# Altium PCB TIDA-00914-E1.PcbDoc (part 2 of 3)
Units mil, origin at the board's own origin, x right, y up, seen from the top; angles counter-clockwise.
Board outline 6575 x 7007.88 mil, 4 copper layers (Top Layer, GND, PWR, Bottom Layer), stack 79.834 mil thick; 302 components, 122 nets, 688 pads, 184 vias.
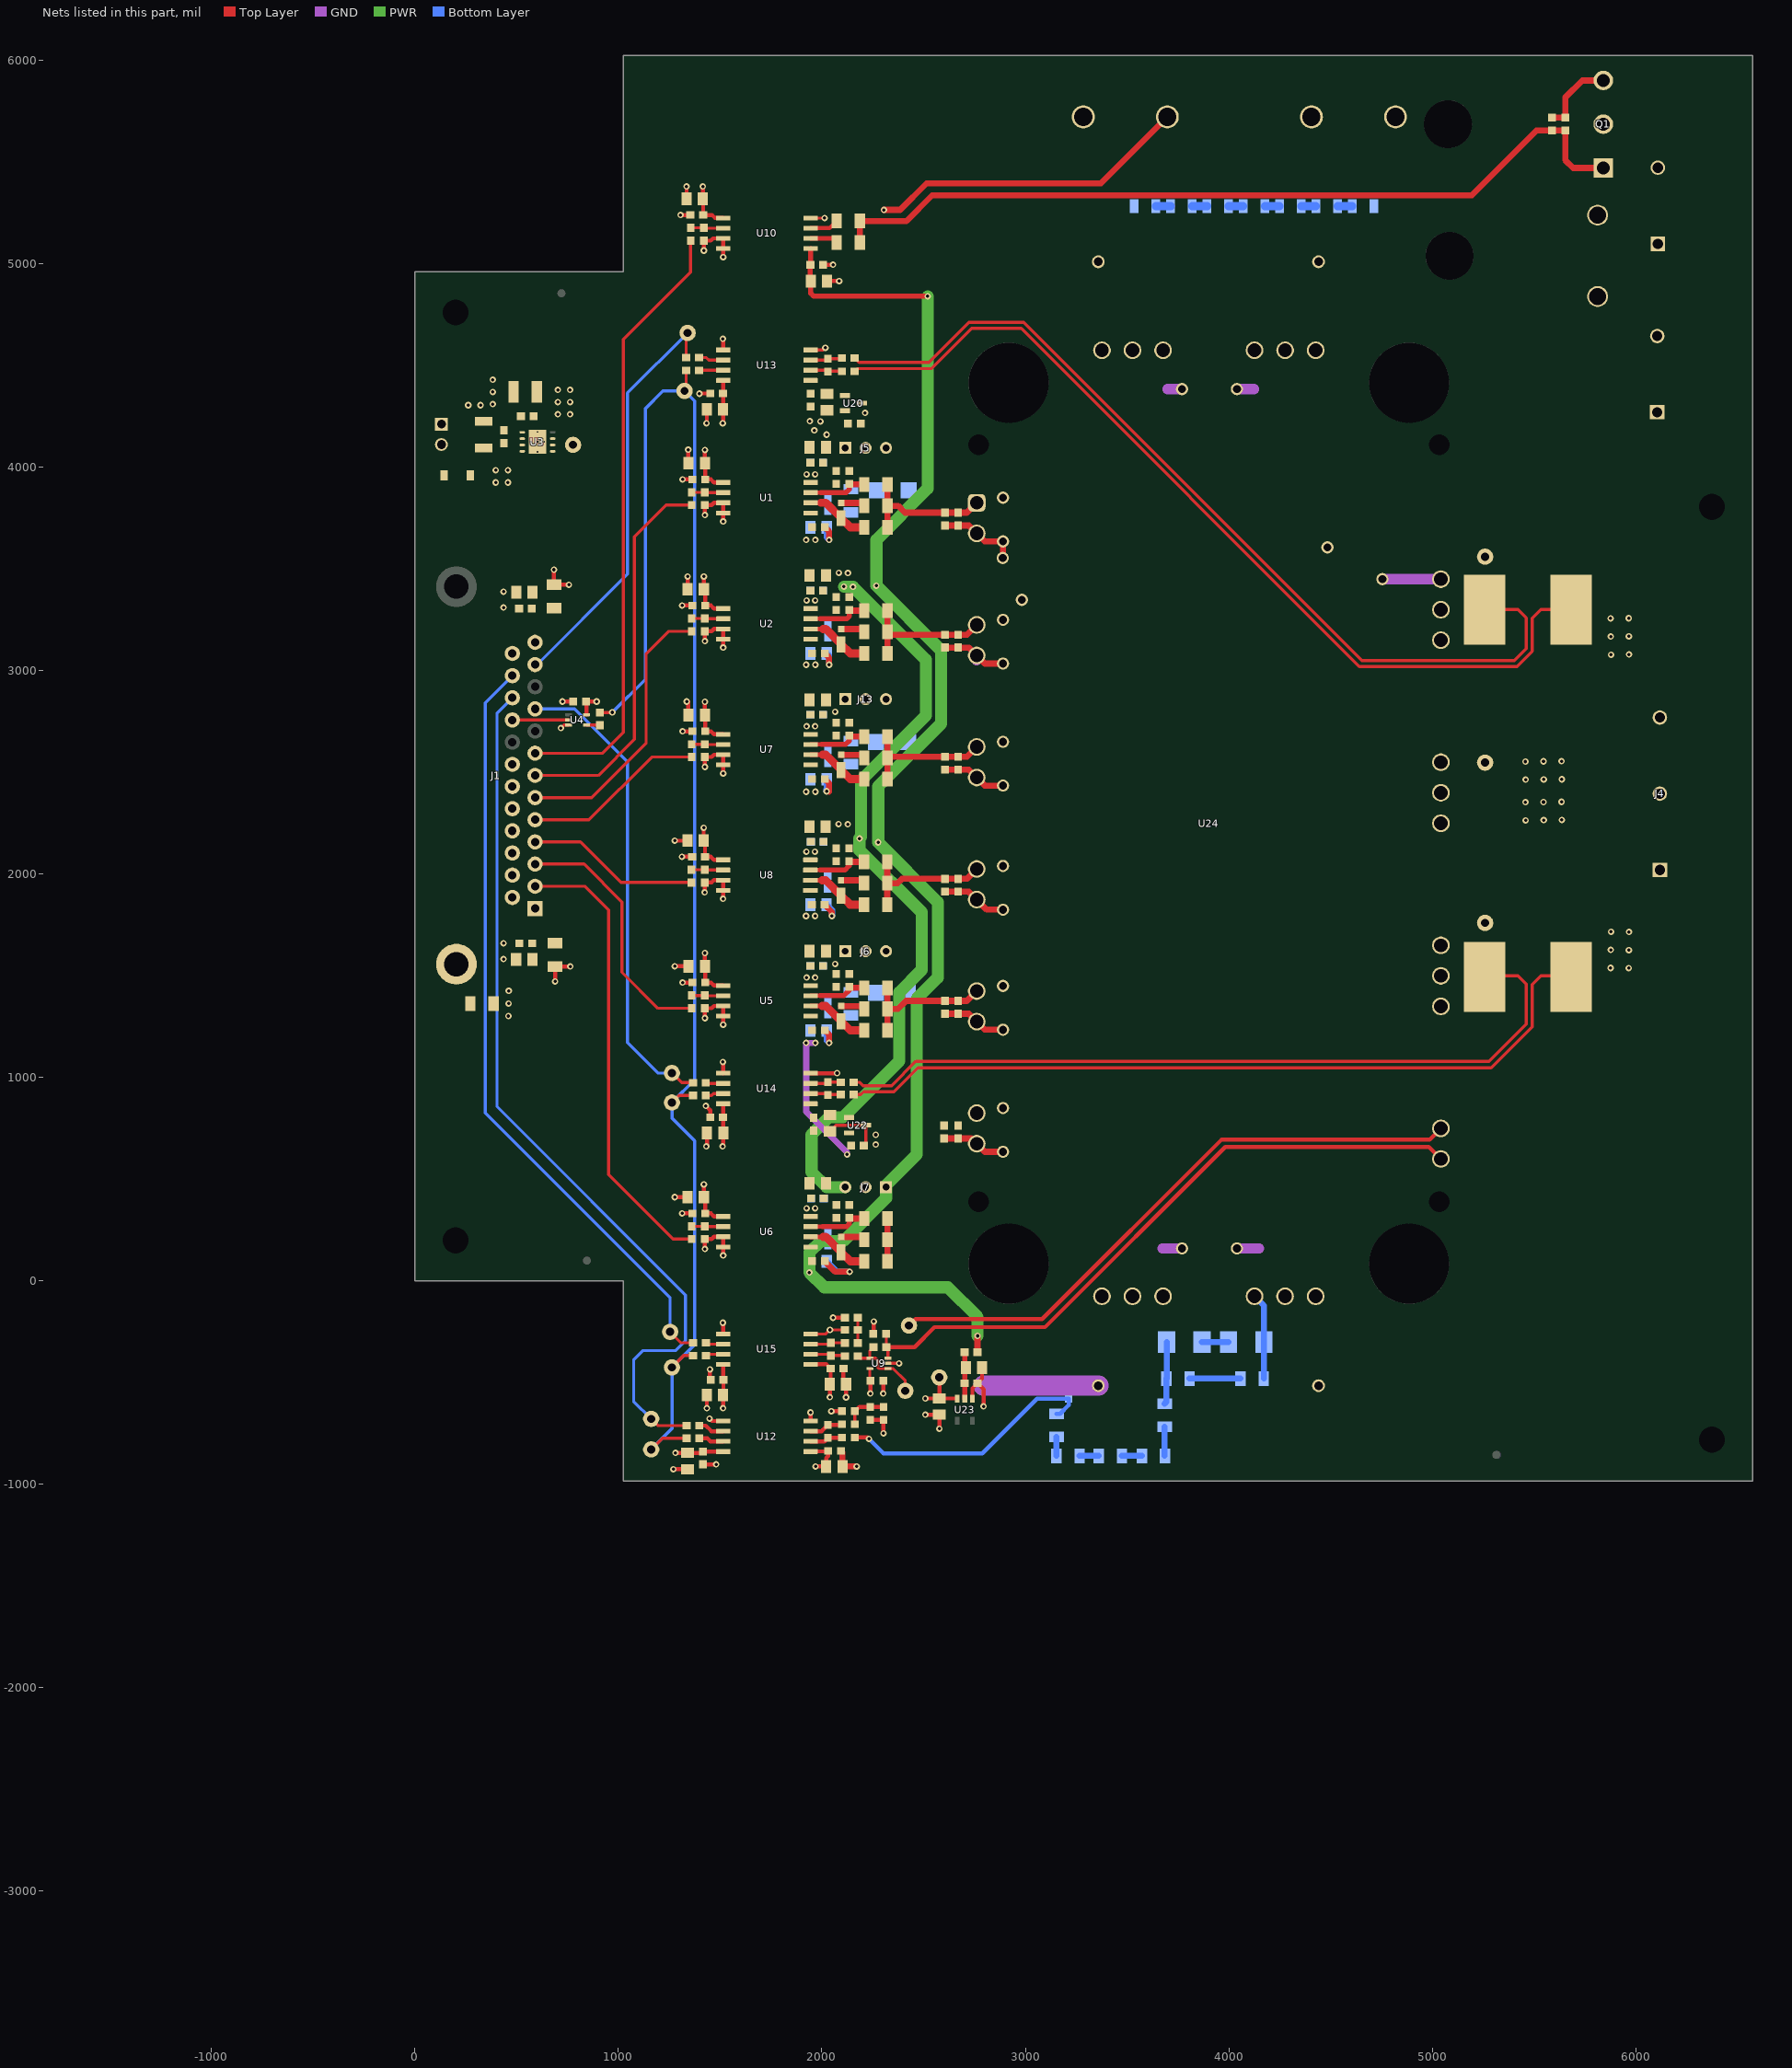
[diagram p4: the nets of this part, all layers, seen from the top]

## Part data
C1 C4 C7 C9 C12 C15 C18 C19 C22 C26 C28 C29 C33 C35 C37 C38 C41 C43 C44 C47 C49 C57 C58 C59 C61 C62 C64 C67 C80 C85 C95 C96: "CAP, CERM, 4.7 µF, 35 V, +/- 10%, X7R, 0805", Cap_Case=0805, Manufacturer=TDK, Supplier Part Number 1=445-7555-1-ND, TempCo=X7R, Tolerance_%=10, Value1="0.002346 ohm", Value2=35V, ValueDisplayed=4.7µF
C2 C6 C8 C11 C14 C17 C21 C25 C27 C30 C36 C42 C63 C65 C66 C68 C70 C71 C79 C82 C87 C89 C91 C94 C97: "CAP, CERM, 0.1 µF, 50 V, +/- 10%, X7R, 0603", Cap_Case=0603, Manufacturer=TDK, Supplier Part Number 1=445-1314-1-ND, TempCo=X7R, Tolerance_%=10, Value1="0.017 ohm", Value2=50V, ValueDisplayed=0.1µF
C3 C13 C16 C20 C23 C31 C32 C34 C39 C40 C45 C46 C48 C50 C51 C52 C53 C54 C56: "CAP, CERM, 0.47 µF, 50 V, +/- 10%, X7R, 0603", Cap_Case=0603, Manufacturer=TDK, Supplier Part Number 1=445-5952-1-ND, TempCo=X7R, Tolerance_%=10, Value1="0.010974 ohm", Value2=50V, ValueDisplayed=0.47µF
C5: "CAP, CERM, 10 µF, 50 V, +/- 10%, X7R, 1210", Cap_Case=1210, Manufacturer="Taiyo Yuden", Supplier Part Number 1=587-3167-1-ND, TempCo=X7R, Tolerance_%=10, Value1=Unknown, Value2=50V, ValueDisplayed=10µF
C10 C101 C102 C103 C104 C105 C106: "CAP, CERM, 12 pF, 50 V, +/- 5%, C0G/NP0, 0603", Cap_Case=0603, Manufacturer=MuRata, Supplier Part Number 1=490-1405-1-ND, TempCo=C0G/NP0, Tolerance_%=5, Value1=Unknown, Value2=50V, ValueDisplayed=12pF
C24: "CAP, CERM, 100 µF, 16 V, +/- 20%, X5R, 1210", Cap_Case=1210, Manufacturer=Kemet, Supplier Part Number 1=399-11270-1-ND, TempCo=X5R, Tolerance_%=20, Value1=Unknown, Value2=16V, ValueDisplayed=100µF
C72 C73 C74 C75 C76 C77 C78: "CAP, CERM, 0.01 µF, 50 V, +/- 5%, C0G/NP0, AEC-Q200 Grade 1, 0603", Cap_Case=0603, Manufacturer=TDK, Supplier Part Number 1=445-6916-1-ND, TempCo=C0G/NP0, Tolerance_%=5, Value1=Unknown, Value2=50V, ValueDisplayed=0.01µF
C81 C83 C84 C92: "CAP, CERM, 47 pF, 50 V, +/- 5%, C0G/NP0, 0603", Cap_Case=0603, Manufacturer=MuRata, Supplier Part Number 1=490-1419-1-ND, TempCo=C0G/NP0, Tolerance_%=5, Value1=Unknown, Value2=50V, ValueDisplayed=47pF
C111 C112: "CAP, Film, 3 µF, 1300 V, +/- 10%, 0.016 ohm, TH", Cap_Case=31.5x18x27.5mm, Manufacturer=TDK, Supplier Part Number 1=B32774D1305K-ND, Tolerance_%=10, Value1="0.016 ohm", Value2=1300V, ValueDisplayed=3µF
"CAUTION HOT SURFACE": library part IEC_HotSurface, "IEC 61010-1 Hot Surface Warning"
D1: "Diode, Schottky, 30 V, 0.5 A, SOD-123", Manufacturer="Diodes Inc.", Supplier Part Number 1=B0530W-FDICT-ND, Value1=0.5A, Value2=0.43V
D2 D3 D4 D5 D6 D7: library part MSS1P3L-M3/89A, "Diode, Schottky, 30 V, 2 A, AEC-Q101, MicroSMP", Manufacturer=Vishay-Semiconductor, Supplier Part Number 1=MSS2P3-M3/89AGICT-ND, Value1=2A, Value2=0.6V
D9: library part FFH60UP40S, "Diode, Ultrafast, 1200 V, 30 A, TH", Manufacturer="Fairchild Semiconductor", Supplier Part Number 1=RHRG30120-ND, Value1=30A, Value2=1.3V
D10 D11: "Diode, Zener, 200 V, 550 mW, SMB", Manufacturer="ON Semiconductor", Power_W=0.55, Supplier Part Number 1=863-1SMB5956BT3G, Value1=0.55W
D12 D13 D14: "Diode, Ultrafast, 1300 V, 1 A, SMA", Manufacturer=Vishay-Semiconductor, Supplier Part Number 1=BYG23T-M3/CT-ND, Value1=1A, Value2=1.9V
"ESD Sensitive": library part ESD_Susceptible, "ESD Susceptible Symbol"
FID1 FID2 FID3 FID4 FID5 FID6: "Fiducial mark.  There is nothing to buy or mount.", Manufacturer=N/A
H1 H2 H3 H4: library part "MH 3_0.5MM", "Mountin hole, NPTH Drill 3.2mm", Manufacturer=N/A
H5 H6 H7 H8: "Standoff, Hex, 0.5\"L #4-40 Nylon", Alternate Manufacturer=-, Manufacturer=Keystone, Supplier Part Number 1=1902CK-ND
J1: "Connector, TH, DB25 parallel port, plastic, right angle", Manufacturer=AMP, Supplier Part Number 1=A33998-ND
J2: "Terminal Block, 2x1, 2.54mm, TH", Manufacturer="TE Connectivity", Supplier Part Number 1=A98333-ND
J3: "Terminal Block, 9.52mm, 2x1, R/A, TH", Color=Green, Current_A=32, Manufacturer="Phoenix Contact", Supplier Part Number 1=277-5951-ND, Voltage_V=1000
J4: "Terminal Block, 9.52mm, 3x1, R/A, TH", Color=Green, Current_A=32A, Manufacturer="Phoenix Contact", Supplier Part Number 1=277-6184-ND, Voltage_V=1000V
J5 J6 J7 J13: "Header, 100mil, 3x1, TH", Manufacturer=Mill-Max, Supplier Part Number 1=ED7203-ND
J8: "Terminal Block, 9.52mm, 2x1, R/A, TH", Color=Green, Current_A=32A, Manufacturer="Phoenix Contact", Supplier Part Number 1=277-5951-ND, Voltage_V=1000V
LBL1: library part THT-14-423-10, "Thermal Transfer Printable Labels, 0.650\" W x 0.200\" H - 10,000 per roll", Alternate Manufacturer=-, Manufacturer=Brady, Supplier Part Number 1=2065596
Logo2: library part Pb-Free
Logo3: library part FCC_disclaimer, "FCC_disclaimer"
LOGO4 LOGO5 LOGO6 LOGO7: library part IEC_HighVoltage, "IEC 61010-1 High Voltage Warning"
Q1: library part "IGW03N120H2, Infineon Technologies", "Transistor, IGBT, 1200 V, 9.9 A, TO-247", Manufacturer="Infineon Technologies", Supplier Part Number 1=NGTB25N120IHLWGOS-ND, Value1="50 A"
R1 R3 R6 R9 R15 R23 R29 R35 R44: "RES, 0, 5%, 0.25 W, 1206", Manufacturer=Vishay-Dale, Power_W=0.25, Supplier Part Number 1=541-0.0ECT-ND, TempCo="200 ppm/C", Tolerance_%=5, Value1=5%, Value2=0.25W, Value_Code=0000, ValueDisplayed=0
R2 R4 R5 R10 R14 R16 R22 R24 R28 R30 R34 R36 R40 R79 R80 R82 R83 R85 R86 R91 R92 R93 R99 R100 R101 R102 R103 R105 R110: "RES, 0, 5%, 0.1 W, 0603", Manufacturer=Vishay-Dale, Power_W=0.1, Supplier Part Number 1=541-0.0GCT-ND, TempCo="200 ppm/C", Tolerance_%=5, Value1=5%, Value2=0.1W, Value_Code=0000, ValueDisplayed=0
R7 R46 R47 R52 R53 R55 R56 R58 R59: "RES, 22, 5%, 0.1 W, 0603", Manufacturer=Vishay-Dale, Power_W=0.1, Supplier Part Number 1=541-22GCT-ND, TempCo="200 ppm/C", Tolerance_%=5, Value1=5%, Value2=0.1W, Value_Code=22R0, ValueDisplayed=22
R8 R90 R107 R109 R139 R140 R141 R142 R143 R144: "RES, 1.00 k, 1%, 0.1 W, 0603", Manufacturer=Vishay-Dale, Power_W=0.1, Supplier Part Number 1=541-1.00KHCT-ND, TempCo="100 ppm/C", Tolerance_%=1, Value1=1%, Value2=0.1W, Value_Code=1k00, ValueDisplayed=1.00k
R11 R13 R17 R18 R19 R21 R25 R27 R31 R33 R37 R39: "RES, 12.0, 1%, 0.25 W, 1206", Manufacturer="Yageo America", Power_W=0.25, Supplier Part Number 1=311-12.0FRCT-ND, TempCo="100 ppm/C", Tolerance_%=1, Value1=1%, Value2=0.25W, Value_Code=12R0, ValueDisplayed=12.0
R12 R20 R26 R32 R38 R96 R112: "RES, 10 k, 5%, 0.1 W, 0603", Manufacturer=Vishay-Dale, Power_W=0.1, Supplier Part Number 1=541-10KGCT-ND, TempCo="200 ppm/C", Tolerance_%=5, Value1=5%, Value2=0.1W, Value_Code=10k0, ValueDisplayed=10k
R41 R42 R43: "RES, 1.00, 1%, 0.25 W, 1206", Manufacturer=Vishay-Dale, Power_W=0.25, Supplier Part Number 1=71-CRCW1206-1-E3, TempCo="100 ppm/C", Tolerance_%=1, Value1=1%, Value2=0.25W, Value_Code=1R00, ValueDisplayed=1.00
R45 R48 R49 R50 R51 R54 R57: library part ERJ-8ENF3573V, "RES, 100 k, 5%, 0.75 W, 1206", Manufacturer=Vishay, Power_W=0.75, Supplier Part Number 1=541-100KUATR-ND, TempCo="200 ppm/C", Tolerance_%=5, Value1=5%, Value2=0.75W, Value_Code=100k
R71 R94: "RES, 16.5, 1%, 0.25 W, 1206", Manufacturer=Vishay-Dale, Power_W=0.25, Supplier Part Number 1=541-16.5FCT-ND, TempCo="100 ppm/C", Tolerance_%=1, Value1=1%, Value2=0.25W, Value_Code=16R5, ValueDisplayed=16.5
R81: "RES, 12.1 k, 1%, 0.1 W, 0603", Manufacturer=Vishay-Dale, Power_W=0.1, Supplier Part Number 1=541-12.1KHCT-ND, TempCo="100 ppm/C", Tolerance_%=1, Value1=1%, Value2=0.1W, Value_Code=12k1, ValueDisplayed=12.1k
R98 R108 R122 R125 R127 R128 R129: "RES, 820 k, 1%, 0.25 W, 1206", Manufacturer="Yageo America", Power_W=0.25, Supplier Part Number 1=311-820KFRCT-ND, TempCo="100 ppm/C", Tolerance_%=1, Value1=1%, Value2=0.25W, Value_Code=820k
R106: "RES, 160 k, 1%, 0.1 W, 0603", Manufacturer=Vishay-Dale, Power_W=0.1, Supplier Part Number 1=541-160KHCT-ND, TempCo="100 ppm/C", Tolerance_%=1, Value1=1%, Value2=0.1W, Value_Code=160k
R118 R120: library part PU5931FKHPA0U2L, "RES, 0.004, 1%, 7 W, AEC-Q200 Grade 0, 15x7.75mm", Manufacturer="Yageo America", Power_W=7, Supplier Part Number 1=YAG4096CT-ND, TempCo="225 ppm/C", Tolerance_%=1, Value1=1%, Value2=7W, Value_Code=L2000, ValueDisplayed=0.004
TP1 TP2 TP3 TP4 TP5 TP6 TP7 TP10 TP11 TP15 TP29 TP31 TP32 TP36 TP37: "Test Point, Miniature, Red, TH", Color=Red, Manufacturer=Keystone, Supplier Part Number 1=36-5000-ND
TP12 TP13 TP14 TP16 TP17 TP18 TP19 TP20 TP21 TP22 TP23 TP24 TP25 TP26 TP27 TP28 TP30 TP33 TP34 TP35: "TEST POINT.  No entry in BOM."
U1 U2 U5 U6 U7 U8: library part CMP-0078847-1, "5-kVRMS Single-Channel Isolated Gate Drivers, DWV0008A (SOIC-8)", Alternate Manufacturer="Texas Instruments", Alternate PartNumber=UCC5310MCDWVR
U3: library part TLV1117-33CDRJR, "LDO with 4.7 to 15 V Input and 3.3 V Output, -40 to 125 degC, 8-Pin SON (DRJ), Green (RoHS & no Sb/Br)", Alternate Manufacturer="Texas Instruments", Alternate PartNumber=Equivalent, Supplier Part Number 1=296-19749-2-ND
U4: "SINGLE SCHMITT-TRIGGER BUFFER, DCK0005A (SOT-5)", Alternate Manufacturer="Texas Instruments", Alternate PartNumber=SN74LVC1G17DCKT
U9: library part LPV521MG, "Nanopower 400nA, 1.8V, R-R I/O CMOS Op Amp, DCK0005A", Alternate Manufacturer="Texas Instruments"
U10: library part CMP-0078838-1, "5-kVRMS Single-Channel Isolated Gate Drivers, DWV0008A (SOIC-8)", Alternate Manufacturer="Texas Instruments", Alternate PartNumber=UCC5320SCDWVR
U12 U13 U14 U15: library part AMC1306M05DWVR, "Small, High-Precision, Reinforced Isolated Delta-Sigma Modulator with Manchester Coded Output, DWV0008A", Alternate Manufacturer="Texas Instruments", Alternate PartNumber=AMC1306M05DWV
U20 U22: "100 mA, Quasi Low-Dropout Linear Voltage Regulator, 3-pin SOT-23, Pb-Free", Manufacturer="Texas Instruments", PackageTopMarking=L0B*XTT, PowerWise=N, Supplier Part Number 1=LM3480IM3-5.0/NOPBTR-ND
U23: "Single Output LDO, 150 mA, Fixed 3.3 V Output, 2.5 to 24 V Input, with Ultra-Low IQ, 5-pin SOT-23 (DBV), -40 to 125 degC, Green (RoHS & no Sb/Br)", Alternate Manufacturer="Texas Instruments", Alternate PartNumber=Equivalent, Supplier Part Number 1=TLV70433DBVR-ND
U24: "IGBT Module,High Power Switching Use Insulated Type, TH", Manufacturer=Mitsubishi, Supplier Part Number 1=835-1148-ND
XF1 XF2: "Fuse Holder, 5AG, TH", Manufacturer=Keystone, Supplier Part Number 1=36-3566-ND
ZZ1: library part AssemblyNoteLabel, Alternate Manufacturer=-
ZZ2 ZZ3 ZZ4: library part AssemblyNote, Alternate Manufacturer=-

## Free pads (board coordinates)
  round 393.7 hole 393.7 unplated mask+5: 1(2917.64,84.41) 1(2917.64,4415.12) 1(4886.14,84.41) 1(4886.14,4415.12)
  round 236.22 hole 236.22 unplated mask+5: 3(5078.01,5686) 3(5085.05,5039)

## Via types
v1: diameter 32, hole 16, Top Layer to Bottom Layer, 179 vias
v2: diameter 19.68, hole 7.87, Top Layer to Bottom Layer, 5 vias

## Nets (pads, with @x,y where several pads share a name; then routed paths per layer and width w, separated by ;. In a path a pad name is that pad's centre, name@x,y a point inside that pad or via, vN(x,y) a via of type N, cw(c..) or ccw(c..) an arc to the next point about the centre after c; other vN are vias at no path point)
3V3: C6.1 C9.1 C11.1 C17.1 C19.1 C22.1 C24.1 C25.1 C27.1 C29.1 C30.1 C36.1 C38.1 C42.1 C44.1 C57.1 C58.2 C59.2 C61.2 C62.2 C63.2 C65.2 C66.2 C68.1 C70.2 TP4.1 U1.1 U2.1 U3.5 U3.6 U3.7 U3.9 U4.5 U5.1 U6.1 U7.1 U8.1 U10.1 U12.8 U13.8 U14.8 U15.8 | length 2691.7
  Top Layer w20: U4.5@843.29,2783.59 843.29,2845.2 C30.1@840.5,2848 v1(893,2848) ; v1(1280,-845) C58.2@1340,-845 1408.5,-845 C63.2@1415,-838.5 C63.2@1415,-838.5 U12.8@1515.17,-838.55 ; v1(1415,5380) C22.1@1415,5320 1416.5,5318.5 C11.1@1416.5,5240 1460,5240 1475,5225 U10.1@1515.43,5225 ; C44.1@1419,2165 v1(1419,2227.99) ; C29.1@1420,412 v1(1420,474.99) ; C9.1@1420,3400 v1(1420,3462.99) ; C44.1@1424,2165 1424,2160 1425.5,2158.5 C42.1@1425.5,2085 1454,2085 1469,2070 U8.1@1514.43,2070 ; C29.1@1425,412 1425,407 1426.5,405.5 C27.1@1426.5,332 1455,332 1470,317 U6.1@1515.43,317 ; C19.1@1425,1541.97 C19.1@1425,1546.97 ; v1(1425,1611.97) C19.1@1425,1546.97 ; C38.1@1425,2776.97 C38.1@1425,2781.97 ; v1(1425,2846.97) C38.1@1425,2781.97 ; C9.1@1425,3400 1425,3395 1426.5,3393.5 C6.1@1426.5,3320 1455,3320 1470,3305 U2.1@1515.43,3305 ; C57.1@1425,4015 C57.1@1425,4020 ; v1(1425,4085) C57.1@1425,4020 ; v1(1512.73,4216.45) 1514.73,4218.45 C59.2@1514.73,4284.45 1514.73,4361.95 C65.2@1514.23,4362.45 1515.17,4363.39 U13.8@1515.17,4426.58 ; v1@1514.16,663.13 1515.5,664.47 C62.2@1515.5,728 ; C62.2@1514.16,728 1514.16,795.55 1514.94,796.33 U14.8@1514.94,871 ; v1(1514.73,-625.55) C61.2@1514.73,-560.55 1516.23,-559.05 C70.2@1516.23,-485.55 1515.17,-484.49 U15.8@1515.17,-410.55 ; U5.1@1515.43,1451.97 1470,1451.97 1455,1466.97 C17.1@1426.5,1466.97 1426.5,1545.47 C19.1@1425,1546.97 ; U7.1@1515.43,2686.97 1470,2686.97 1455,2701.97 C36.1@1426.5,2701.97 1426.5,2780.47 C38.1@1425,2781.97 ; U1.1@1515.43,3925 1470,3925 1455,3940 C68.1@1426.5,3940 1426.5,4018.5 C57.1@1425,4020
  other v1: 1512.16,661.13 702,4260 762,4260 702,4320 762,4320 702,4380 762,4380
  other v2: 602,4075.79 568.54,4125 602,4125 635.46,4125 602,4174.21
3V3_VDC: C64.2 C67.2 C79.1 C82.2 C91.2 C95.1 R81.1 R90.2 R106.1 TP7.1 U9.5 U12.1 U15.1 U23.3 | length 1005.6
  Top Layer w15: C79.1@2235.71,-487.2 U9.5@2235.71,-430.59
  Top Layer w20: U12.1@1944.3,-838.55 1945.12,-837.73 2010.42,-837.73 ; U15.1@1944.3,-410.55 1945.12,-409.73 2022.42,-409.73 C91.2@2043.24,-430.55 2043.24,-503.76 C67.2@2039,-508 v1(2039,-571) ; v1(1969,-912) C64.2@2021,-912 2021,-871 2030.77,-861.23 C82.2@2030.77,-835.95 ; v1(2046.5,-639.99) 2047,-639.5 R81.1@2098.5,-639.5 ; v1(2054.73,-180.55) R90.2@2113.24,-180.55 ; C79.1@2235.71,-487.2 C79.1@2238.5,-490 v1(2238.5,-553) ; R106.1@2255.27,-257.95 v1(2255.27,-199.45) ; v1(2508.33,-577.68) C95.1@2577.33,-577.68 ; TP7.1@2577,-474 2577.33,-474.33 C95.1@2577.33,-577.68 ; TP7.1@2577.33,-460.95 TP7.1@2579.73,-458.55 ; U23.3@2664.93,-578.55 2664.06,-577.68 C95.1@2577.33,-577.68
5V0: C5.1 C14.1 D1.1 R1.1 R6.1 U3.2 U3.3 U3.4 | length 296.1
  Top Layer w20: R6.1@683,3422.09 756.91,3422.09 v1(757,3422.17) ; v1(683,3496.17) 683.09,3496.09 R6.1@683.09,3422.17 ; R1.1@688.91,1546 688.91,1472.09 v1(689,1472) ; R1.1@689,1545.91 762.91,1545.91 v1(763,1546)
  other v1: 397,3925 457,3925 397,3985 457,3985
BRAKE_IGBT_GATE: C78.1 Q1.1 R71.2 R94.2 R96.2 | length 4104.4
  Top Layer w30: R71.2@2187.09,5105 R94.2@2187.09,5210 2416,5210 2542,5336 5193.99,5336 5513,5655.01 R96.2@5589,5655.01 C78.1@5654,5655.01 5654,5510 5693,5471 Q1.1@5841,5471
GND: C1.1 C2.1 C5.2 C6.2 C7.2 C8.2 C9.2 C10.2 C11.2 C14.2 C17.2 C19.2 C22.2 C24.2 C25.2 C27.2 C29.2 C30.2 C36.2 C38.2 C42.2 C44.2 C57.2 C58.1 C59.1 C61.1 C62.1 C63.1 C65.1 C66.1 C68.2 C70.1 C101.2 C102.2 C103.2 C104.2 C105.2 C106.2 J1.14 J1.15 J1.16 J1.17 J1.18 J1.19 J1.20 J1.25 J2.1 R44.1 U1.3 U1.4 U2.3 U2.4 U3.1 U4.3 U5.3 U5.4 U6.3 U6.4 U7.3 U7.4 U8.3 U8.4 U10.3 U10.4 U12.5 U13.5 U14.5 U15.5 | length 3323.7
  Top Layer w15: v1(717,2718) 731.41,2732.41 U4.3@754.71,2732.41
  Top Layer w20: v1@460,1364 v1(460.09,1364.09) ; v1(725,2848) C30.2@777.5,2848 ; v1(1270,-925) 1279.72,-925 C58.1@1340,-925 ; v1(1277.01,412) C29.2@1340,412 ; v1(1277.01,1546.97) C19.2@1343.5,1546.97 ; v1(1277.01,2164) C44.2@1340,2164 ; v1@1302.99,5240 v1(1305,5240) C11.2@1353.5,5240 ; v1(1311.99,2085) C42.2@1362.5,2085 ; v1(1312.99,332) C27.2@1363.5,332 ; v1@1312.99,1466.97 v1(1315,1466.97) C17.2@1363.5,1466.97 ; v1@1312.99,2701.97 v1(1315,2701.97) C36.2@1363.5,2701.97 ; v1(1312.99,3320) C6.2@1363.5,3320 ; v1@1312.99,3940 v1(1315,3940) C68.2@1363.5,3940 ; C22.2@1335,5320 v1(1335,5380) ; v1(1336,2848) v1@1338.96,2848 ; C9.2@1340,3400 v1(1340,3462.99) ; v1(1343,4086) 1343.5,4086.5 C57.2@1343.5,4020 ; C38.2@1343.5,2781.97 v1@1343.5,2848.47 ; v1(1397.73,4361.45) 1398.73,4362.45 C65.1@1451.24,4362.45 ; C63.1@1414.05,-900.27 1415.55,-901.76 v1(1480.55,-901.76) ; v1@1420,5062.99 v1(1420,5065) C10.2@1420,5113.5 1453.5,5113.5 1465,5125 U10.3@1515.43,5125 U10.4@1515.43,5075 1515.43,5033.46 v1(1515,5033.03) ; v1@1424,1907.99 v1(1424,1910) C103.2@1424,1958.5 1457.5,1958.5 1469,1970 U8.3@1514.43,1970 U8.4@1514.43,1920 1514.43,1878.46 v1(1514,1878.03) ; v1@1425,154.99 v1(1425,157) C105.2@1425,205.5 1458.5,205.5 1470,217 U6.3@1515.43,217 U6.4@1515.43,167 1515.43,125.46 v1(1515,125.03) ; v1@1425,1289.96 v1(1425,1291.97) C106.2@1425,1340.47 1458.5,1340.47 1470,1351.97 U5.3@1515.43,1351.97 U5.4@1515.43,1301.97 1515.43,1260.43 v1(1515,1260) ; v1@1425,2524.96 v1(1425,2526.97) C104.2@1425,2575.47 1458.5,2575.47 1470,2586.97 U7.3@1515.43,2586.97 U7.4@1515.43,2536.97 1515.43,2495.43 v1(1515,2495) ; v1@1425,3142.99 v1(1425,3145) C101.2@1425,3193.5 1458.5,3193.5 1470,3205 U2.3@1515.43,3205 U2.4@1515.43,3155 1515.43,3113.46 v1(1515,3113.03) ; v1@1425,3762.99 v1(1425,3765) C102.2@1425,3813.5 1458.5,3813.5 1470,3825 U1.3@1515.43,3825 U1.4@1515.43,3775 1515.43,3733.46 v1(1515,3733.03) ; v1(1429.77,860.55) 1451.01,839.31 C66.1@1451.01,804 ; v1(1432.73,4216.45) 1434.73,4218.45 C59.1@1434.73,4284.45 ; v1@1434.16,663.13 1435.5,664.47 C62.1@1435.5,728 ; C62.1@1434.16,728 C62.1@1434.16,729.13 ; v1(1434.73,-625.55) C61.1@1434.73,-560.55 C61.1@1436.23,-559.05 ; v1(1448,-677) 1459.55,-688.55 U12.5@1515.17,-688.55 ; v1(1450,-435) 1450,-482.31 C70.1@1453.24,-485.55 C70.1@1454.73,-487.05 ; v1(1513.09,1076.25) 1514.59,1074.76 U14.5@1514.59,1021.25 ; v1(1513.67,-205.55) 1515.17,-207.05 U15.5@1515.17,-260.55 ; v1(1513.67,4631.58) 1515.17,4630.08 U13.5@1515.17,4576.58
  other v1: 1432.16,661.13 459.17,1302.17 461,1426 435,1582 435,1660 435,3310 435,3388 262,4305 322,4305 382.77,4309.98 382.77,4369.98 382.77,4429.98
GND_UT: C18.1 C20.1 C21.1 C23.2 C26.2 C74.2 C85.1 C89.1 J6.2 R14.2 R16.2 R112.1 TP18.1 U14.4 U22.3 U24.10 | length 863.2
  Top Layer w15: C85.1@2039.77,735.55 2069.77,765.55 U22.3@2216.11,765.55 C21.1@2216.11,675.39
  Top Layer w20: U14.4@1944.07,1021 2074.22,1021 v1(2074.77,1021.55)
  Top Layer w30: C23.2@2014.5,1231.97 2036,1210.47 v1@2036,1170.97 ; R112.1@2605,1313.5 C74.2@2670,1313.5 2722.2,1313.5 U24.10@2761.14,1274.57 2800.71,1235 TP18.1@2890,1235
  Bottom Layer w30: C26.2@2024,1230.97 2024,1181.97 v1(2036,1169.97)
  other v1: 2264.77,670.55 2264.77,718.55 2065,1558
GND_VT: C37.1 C39.1 C40.2 C41.2 C73.2 J13.2 R28.2 R30.2 R32.1 TP16.1 U24.6 | length 446.8
  Top Layer w30: C40.2@2014.5,2466.97 2036,2445.47 v1@2036,2405.97 ; R32.1@2605,2513.5 C73.2@2670,2513.5 2722.2,2513.5 U24.6@2761.14,2474.57 2800.71,2435 TP16.1@2890,2435
  Bottom Layer w30: v1(2023,2407) 2023,2415.97 2024,2416.97 C41.2@2024,2465.97
  other v1: 2065,2798
GND_WT: C3.2 C4.2 C15.1 C16.1 C71.1 C72.2 C80.1 C87.1 J5.2 R2.2 R4.2 R20.1 TP13.1 TP30.1 U13.4 U20.3 U24.2 | length 611.8
  Top Layer w15: U13.4@1944.3,4576.58 2006.58,4576.58 v1(2017,4587)
  Top Layer w30: C3.2@2014.5,3705 2036,3683.5 v1@2036,3644 ; R20.1@2605,3713.5 C72.2@2670,3713.5 2722.2,3713.5 U24.2@2761.14,3674.57 2800.71,3635 TP13.1@2890,3635 2890,3555 TP30.1@2889,3554
  Bottom Layer w30: C4.2@2024,3704 2024,3655 v1(2036,3643)
  other v1: 2023,4160 1963,4181 1993,4225 1941,4226 2212,4267
MCLK: R7.2 R46.2 R52.2 R55.2 R58.2 TP2.1 TP6.1 TP11.1 TP15.1 | length 7802.4
  Top Layer w15: v1@969.5,2794.5 v1(970,2795) ; TP6.1@1325,4375 1333.01,4383.01 R52.2@1333.01,4476
  Top Layer w16: R7.2@909,2794.5 v1@969.5,2794.5 ; TP2.1@1161,-828 1216,-773 R55.2@1335.01,-773 ; TP15.1@1263,-425 1321,-367 R58.2@1367.01,-367 ; TP11.1@1263,877 1297.55,911.55 R46.2@1366.46,911.55
  Bottom Layer w16: v1(970,2795) 1132,2957 1132,4288 1219,4375 TP6.1@1325,4375 1375,4325 1375,989 TP11.1@1263,877 1263,801 1375,689 1375,-313 TP15.1@1263,-425 1263,-726 TP2.1@1161,-828
MDATA_TMP: J1.24 R59.2 TP3.1 | length 3792.7
  Top Layer w15: TP3.1@1254,-250 1308,-304 R59.2@1367.01,-304
  Bottom Layer w15: J1.24@478.5,2975.5 345,2842 345,826 1254,-83 TP3.1@1254,-250
MDATA_U: J1.10 R47.2 TP10.1 | length 2345.8
  Top Layer w15: TP10.1@1263,1022 1310.45,974.55 R47.2@1366.46,974.55
  Bottom Layer w15: J1.10@590.5,2812 785,2812 1045,2552 1045,1171.32 1194.32,1022 TP10.1@1263,1022
MDATA_VDC: J1.23 R56.2 TP1.1 | length 4382
  Top Layer w15: TP1.1@1161,-678 1194,-711 R56.2@1335.01,-711
  Bottom Layer w15: J1.23@478.5,2866.5 403.5,2791.5 403.5,856.5 1330,-70 1330,-294 1282,-342 1122,-342 1075,-389 1075,-592 TP1.1@1161,-678
MDATA_W: J1.12 R53.2 TP5.1 | length 2069.8
  Top Layer w15: R53.2@1333.01,4532 R53.2@1333.01,4539 1333.01,4653.01 TP5.1@1335,4655
  Bottom Layer w15: J1.12@590.5,3030 600,3030 1045,3475 1045,4365 TP5.1@1340,4660
NetC1_2: C1.2 C2.2 J1.1 R1.2
NetC7_1: C7.1 C8.1 J1.13 R6.2
NetC10_1: C10.1 R8.1 U10.2 | length 161.1
  Top Layer w15: R8.1@1355,5176.5 C10.1@1420,5176.5 1421.5,5175 U10.2@1515.43,5175
NetC12_2: C12.2 C13.2 R10.1 R102.2 U2.8
  other v1: 1925,3345 1967,3345
NetC15_2: C15.2 C16.2 R4.1 R100.2 U1.8
  other v1: 1925,3965 1967,3965
NetC18_2: C18.2 C20.2 R16.1 R99.2 U5.8
  other v1: 1925,1491.97 1967,1491.97
NetC28_2: C28.2 C31.2 R24.1 R101.2 U6.8
  other v1: 1925,357 1967,357
NetC37_2: C37.2 C39.2 R30.1 R103.2 U7.8
  other v1: 1925,2726.97 1967,2726.97
NetC43_2: C43.2 C45.2 R36.1 R105.2 U8.8
  other v1: 1924,2110 1966,2110
NetC80_2: C80.2 C87.2 U13.1 U20.1
NetC81_1: C81.1 R83.2 U12.2 | length 162.1
  Top Layer w20: U12.2@1944.3,-788.55 2012.44,-788.55 C81.1@2030,-770.99 2097.01,-770.99 R83.2@2098.5,-769.5
NetC81_2: C81.2 R82.2 U12.3 | length 167.5
  Top Layer w20: U12.3@1944.3,-738.55 1998.6,-738.55 2003.84,-733.31 C81.2@2029.15,-708 ; C81.2@2030,-708 2095,-708 R82.2@2098.5,-704.5
NetC83_1: C83.1 R86.2 U13.2 | length 157.2
  Top Layer w15: U13.2@1944.3,4476.58 2023.24,4476.58 C83.1@2029.73,4470.08 2031.23,4471.58 R86.2@2098.24,4471.58
NetC83_2: C83.2 R85.2 U13.3 | length 153.1
  Top Layer w15: U13.3@1944.3,4526.58 C83.2@2023.24,4526.58 ; C83.2@2029.73,4533.07 R85.2@2094.73,4533.07
  Top Layer w20: C83.2@2023.24,4526.58 C83.2@2029.73,4533.07
NetC84_1: C84.1 R80.2 U14.2 | length 157.2
  Top Layer w15: U14.2@1943.72,921.25 2022.66,921.25 2029.16,914.76 2030.65,916.25 R80.2@2097.66,916.25
NetC84_2: C84.2 R79.2 U14.3 | length 153.1
  Top Layer w15: U14.3@1943.72,971.25 C84.2@2022.66,971.25 ; C84.2@2029.16,977.75 R79.2@2094.16,977.75
  Top Layer w20: C84.2@2022.66,971.25 C84.2@2029.16,977.75
NetC85_2: C85.2 C89.2 U14.1 U22.1
NetC92_1: C92.1 R93.2 U15.2 | length 172.2
  Top Layer w15: U15.2@1944.3,-360.55 2038.24,-360.55 C92.1@2044.73,-367.05 2046.23,-365.55 R93.2@2113.24,-365.55
NetC92_2: C92.2 R92.2 U15.3 | length 172.2
  Top Layer w15: U15.3@1944.3,-310.55 2038.24,-310.55 C92.2@2044.73,-304.05 2111.74,-304.05 R92.2@2113.24,-305.55
NetC94_2: C94.2 R81.2 R82.1 R107.2 | length 213.8
  Top Layer w15: R82.1@2161.5,-704.5 R81.2@2161.5,-639.5
  Top Layer w20: R81.2@2162.82,-640.82 2183.64,-620 R107.2@2238,-620 C94.2@2303,-620
NetC96_1: C96.1 C97.1 R110.2 U23.2 | length 232.6
  Top Layer w25: R110.2@2701.84,-350.68 2701.84,-421.19 C96.1@2707.33,-426.68 2701.84,-432.18 C97.1@2701.84,-502.68 2702.33,-503.18 U23.2@2702.33,-578.55
NetC101_1: C101.1 R139.1 U2.2 | length 156.1
  Top Layer w15: R139.1@1360,3256.5 C101.1@1425,3256.5 1426.5,3255 U2.2@1515.43,3255
NetC102_1: C102.1 R140.1 U1.2 | length 156.1
  Top Layer w15: R140.1@1360,3876.5 C102.1@1425,3876.5 1426.5,3875 U1.2@1515.43,3875
NetC103_1: C103.1 R141.1 U8.2 | length 156.1
  Top Layer w15: R141.1@1359,2021.5 C103.1@1424,2021.5 1425.5,2020 U8.2@1514.43,2020
NetC104_1: C104.1 R142.1 U7.2 | length 156.1
  Top Layer w15: R142.1@1360,2638.47 C104.1@1425,2638.47 1426.5,2636.97 U7.2@1515.43,2636.97
NetC105_1: C105.1 R144.1 U6.2 | length 156.1
  Top Layer w15: R144.1@1360,268.5 C105.1@1425,268.5 1426.5,267 U6.2@1515.43,267
NetC106_1: C106.1 R143.1 U5.2 | length 156.1
  Top Layer w15: R143.1@1360,1403.47 C106.1@1425,1403.47 1426.5,1401.97 U5.2@1515.43,1401.97
NetD1_2: D1.2 J2.2
NetD2_1: D2.1 R13.1 U2.6 | length 313.1
  Top Layer w22: U2.6@1944.57,3205 2007,3205
  Top Layer w40: 2007,3205 2019.41,3205 D2.1@2095,3129.41 2139.41,3085 R13.1@2207.91,3085
NetD2_2: D2.2 R11.1 | length 98.7
  Top Layer w30: D2.2@2095,3204.21 R11.1@2193.7,3204.21
NetD3_1: D3.1 R19.1 U1.6 | length 313.1
  Top Layer w22: U1.6@1944.57,3825 1996,3825
  Top Layer w40: 1996,3825 2019.41,3825 D3.1@2095,3749.41 2139.41,3705 R19.1@2207.91,3705
NetD3_2: D3.2 R17.1 | length 98.7
  Top Layer w30: D3.2@2095,3824.21 R17.1@2193.7,3824.21
NetD4_1: D4.1 R21.1 U5.6 | length 313.1
  Top Layer w22: U5.6@1944.57,1351.97 2002,1351.97
  Top Layer w40: 2002,1351.97 2019.41,1351.97 D4.1@2095,1276.38 2139.41,1231.97 R21.1@2207.91,1231.97
NetD4_2: D4.2 R18.1 | length 118.8
  Top Layer w30: D4.2@2095,1351.18 2193.7,1351.18 R18.1@2207.91,1336.97
NetD5_1: D5.1 R27.1 U6.6 | length 313.1
  Top Layer w22: U6.6@1944.57,217 2007,217
  Top Layer w40: 2007,217 2019.41,217 D5.1@2095,141.41 2139.41,97 R27.1@2207.91,97
NetD5_2: D5.2 R25.1 | length 98.7
  Top Layer w30: D5.2@2095,216.21 R25.1@2193.7,216.21
NetD6_1: D6.1 R33.1 U7.6 | length 313.1
  Top Layer w22: U7.6@1944.57,2586.97 2004,2586.97
  Top Layer w40: 2004,2586.97 2019.41,2586.97 D6.1@2095,2511.38 2139.41,2466.97 R33.1@2207.91,2466.97
NetD6_2: D6.2 R31.1 | length 98.7
  Top Layer w30: D6.2@2095,2586.18 R31.1@2193.7,2586.18
NetD7_1: D7.1 R39.1 U8.6 | length 313.1
  Top Layer w22: U8.6@1943.57,1970 2002,1970
  Top Layer w40: 2002,1970 2018.41,1970 D7.1@2094,1894.41 2138.41,1850 R39.1@2206.91,1850
NetD7_2: D7.2 R37.1 | length 98.7
  Top Layer w30: D7.2@2094,1969.21 R37.1@2192.7,1969.21
NetD9_2: D9.2 J3.1 Q1.2
NetD10_2: D10.2 D11.1 | length 130
  Bottom Layer w30: D11.1@3868.75,-300.55 D10.2@3998.73,-300.55
NetD11_2: D11.2 R108.1 R122.2 | length 306.4
  Bottom Layer w30: R122.2@3685,-602.91 3692.91,-595 R108.1@3692.91,-480 3694.73,-478.18 D11.2@3694.73,-300.55
NetD12_1: D12.1 R41.2
NetD13_1: D13.1 R42.2
NetD14_1: D14.1 R43.2
NetJ1_22: J1.22 U4.2 | length 276.4
  Top Layer w15: J1.22@478.5,2757.5 754.21,2757.5 U4.2@754.71,2758
NETJ1_26: J1.26 R44.2
NetJ4_2: J4.2 TP31.1 U24.24 U24.25 U24.26
  other v1: 5459,2264 5548,2265 5637,2266 5458,2353 5547,2354 5636,2355 5459,2464 5548,2465 5637,2466 5458,2553 5547,2554 5636,2555
NetR2_1: R2.1 R3.1 U1.7 | length 298.3
  Top Layer w20: U1.7@1944.57,3875 1995,3875
  Top Layer w25: 1995,3875 2118,3875 2135,3892 R2.1@2135,3918.5
  Top Layer w30: R2.1@2135,3918.5 2138.5,3915 R3.1@2207.91,3915
NetR5_1: R5.1 R9.1 U2.7 | length 300.7
  Top Layer w20: U2.7@1944.57,3255 1993,3255
  Top Layer w25: 1993,3255 2093.87,3255 2122,3255 2135,3268 R5.1@2135,3298.5
  Top Layer w30: R5.1@2135,3298.5 2138.5,3295 R9.1@2207.91,3295
NetR7_1: R7.1 U4.4 | length 66.1
  Top Layer w15: U4.4@843.29,2732.41 908.09,2732.41 R7.1@909,2731.5
NetR14_1: R14.1 R15.1 U5.7 | length 285.9
  Top Layer w20: U5.7@1944.57,1401.97 1993,1401.97
  Top Layer w25: 1993,1401.97 2106.97,1401.97 2135,1430 R14.1@2135,1445.47
  Top Layer w30: R14.1@2139.5,1440.97 R15.1@2207.91,1440.97
NetR22_1: R22.1 R23.1 U6.7 | length 300.1
  Top Layer w20: U6.7@1944.57,267 2004,267
  Top Layer w25: 2004,267 2121,267 2135,281 R22.1@2135,310.5
  Top Layer w30: R22.1@2135,310.5 2138.5,307 R23.1@2207.91,307
NetR28_1: R28.1 R29.1 U7.7 | length 297.6
  Top Layer w20: U7.7@1944.57,2636.97 1998,2636.97
  Top Layer w25: 1998,2636.97 2115.97,2636.97 2135,2656 R28.1@2135,2680.47
  Top Layer w30: R28.1@2135,2680.47 2139.5,2675.97 R29.1@2207.91,2675.97
NetR34_1: R34.1 R35.1 U8.7 | length 296.1
  Top Layer w20: U8.7@1943.57,2020 1993,2020
  Top Layer w25: 1993,2020 2113.18,2020 2134,2040.82 R34.1@2134,2063.5
  Top Layer w30: R34.1@2134,2063.5 2137.5,2060 R35.1@2206.91,2060
NetR40_1: R40.1 R106.2 U9.3 U24.19 | length 3281.4
  Top Layer w15: R106.2@2315.95,-259.73 2316.5,-260.28 R40.1@2316.5,-325 2324.29,-332.8 U9.3@2324.29,-379.41
  Top Layer w20: R40.1@2316.5,-325 2455.5,-325 2553.5,-227 3097,-227 3983,659 4983.4,659 U24.19@5042.64,599.76
NetR40_2: R40.2 R93.1 TP37.1 U9.1 U9.4 | length 415.5
  Top Layer w15: R93.1@2176.5,-370 2185.91,-379.41 U9.4@2235.71,-379.41 ; R40.2@2253.5,-325 2235.71,-342.8 U9.4@2235.71,-379.41 ; TP37.1@2410,-540 2410,-490 2350.59,-430.59 U9.1@2324.29,-430.59 2280.59,-430.59 2275,-425 2275,-390 2264.41,-379.41 U9.4@2235.71,-379.41
NetR45_2: R45.2 R48.1 | length 72.2
  Bottom Layer w40: R48.1@4534.65,5283.69 R45.2@4606.85,5283.69
NetR46_1: R46.1 U14.7 | length 89.4
  Top Layer w15: R46.1@1429.45,911.55 1457.55,911.55 1467,921 U14.7@1514.94,921
NetR47_1: R47.1 U14.6 | length 87
  Top Layer w15: R47.1@1429.45,974.55 1433,971 U14.6@1514.94,971
NetR48_2: R48.2 R49.1 | length 72.2
  Bottom Layer w40: R49.1@4356.15,5283.69 R48.2@4428.35,5283.69
NetR49_2: R49.2 R50.1 | length 72.2
  Bottom Layer w40: R50.1@4177.65,5283.69 R49.2@4249.85,5283.69
NetR50_2: R50.2 R57.2 | length 72.2
  Bottom Layer w40: R57.2@3999.15,5283.69 R50.2@4071.35,5283.69
NetR51_2: R51.2 R54.1 | length 72.2
  Bottom Layer w40: R51.2@3642.15,5283.69 R54.1@3714.35,5283.69
NetR52_1: R52.1 U13.7 | length 122.3
  Top Layer w15: R52.1@1396,4469 1403.58,4476.58 U13.7@1515.17,4476.58
NetR53_1: R53.1 U13.6 | length 124.3
  Top Layer w15: R53.1@1396,4539 1432,4539 1444.42,4526.58 U13.6@1515.17,4526.58
NetR54_2: R54.2 R57.1 | length 72.2
  Bottom Layer w40: R54.2@3820.65,5283.69 R57.1@3892.85,5283.69
NetR55_1: R55.1 U12.7 | length 123.6
  Top Layer w20: R55.1@1398,-773 1437,-773 1452.55,-788.55 U12.7@1515.17,-788.55
NetR56_1: R56.1 U12.6 | length 128.6
  Top Layer w20: R56.1@1398,-711 1429.45,-711 1457,-738.55 U12.6@1515.17,-738.55
NetR58_1: R58.1 U15.7 | length 91.3
  Top Layer w15: R58.1@1426.5,-367 1432.95,-360.55 U15.7@1515.17,-360.55
NetR59_1: R59.1 U15.6 | length 90.5
  Top Layer w15: R59.1@1426.5,-315 1430.95,-310.55 U15.6@1515.17,-310.55
NetR71_1: R71.1 U10.6 | length 136.6
  Top Layer w22: U10.6@1944.57,5125 2052.91,5125 R71.1@2072.91,5105
NetR83_1: R83.1 R109.2 R129.1 | length 1304.8
  Top Layer w20: R83.1@2161.5,-769.5 2224.5,-769.5 v1(2231,-776)
  Bottom Layer w20: v1(2231,-776) 2303,-848 2789,-848 3058,-579 R109.2@3213,-579 3213,-611 3171.09,-652.91 R129.1@3153,-652.91
NetR90_1: R90.1 R91.2 R92.1 | length 125
  Top Layer w15: R92.1@2176.23,-305.55 R91.2@2176.23,-240.55 R90.1@2176.23,-180.55
NetR94_1: R94.1 U10.7 | length 142.8
  Top Layer w20: U10.7@1944.57,5175 2037.91,5175 R94.1@2072.91,5210
NetR98_1: R98.1 R108.2 | length 250.8
  Bottom Layer w30: R108.2@3807.09,-480 R98.1@4057.91,-480
NetR122_1: R122.1 R125.2 | length 140.8
  Bottom Layer w30: R125.2@3685,-857.91 R122.1@3685,-717.09
NetR125_1: R125.1 R127.2 | length 97.9
  Bottom Layer w30: R127.2@3475,-860 R125.1@3572.91,-860
NetR127_1: R127.1 R128.2 | length 93.7
  Bottom Layer w30: R128.2@3267.09,-860 R127.1@3360.83,-860
NetR128_1: R128.1 R129.2 | length 92.9
  Bottom Layer w30: R128.1@3152.91,-860 3153,-859.91 R129.2@3153,-767.09
PWM_BRAKE+: J1.8 R8.2 | length 3030.4
  Top Layer w15: J1.8@590.5,2594 922,2594 1024,2696 1024,4628 1355,4959 R8.2@1355,5113.5
PWM_UB+: J1.2 R144.2 | length 2250.1
  Top Layer w15: J1.2@590.5,1940 835,1940 952.2,1822.8 952.2,521.8 1268.5,205.5 R144.2@1360,205.5
PWM_UT+: J1.3 R143.2 | length 1265.1
  Top Layer w15: J1.3@590.5,2049 831,2049 1018,1862 1018,1517 1194.53,1340.47 R143.2@1360,1340.47
PWM_VB+: J1.4 R141.2 | length 851.1
  Top Layer w15: J1.4@590.5,2158 813,2158 1012.5,1958.5 R141.2@1359,1958.5
PWM_VT+: J1.5 R142.2 | length 897.3
  Top Layer w15: J1.5@590.5,2267 855,2267 1163.47,2575.47 R142.2@1360,2575.47
PWM_WB+: J1.6 R139.2 | length 1364.7
  Top Layer w15: J1.6@590.5,2376 869,2376 1136,2643 1136,3081 1248.5,3193.5 R139.2@1360,3193.5
PWM_WT+: J1.7 R140.2 | length 1903.2
  Top Layer w15: J1.7@590.5,2485 901,2485 1078,2662 1078,3658 1233.5,3813.5 R140.2@1360,3813.5
U_BOT: C75.1 R12.2 R23.2 R25.2 R27.2 TP19.1 U24.11 | length 210
  Top Layer w30: R27.2@2322.09,97 R25.2@2322.09,202 R23.2@2322.09,307
U_PHASE: J4.1 R80.1 R120.2 | length 3890.6
  Top Layer w15: R80.1@2156,916 2192,916 2206,930 2355,930 2472,1047 5289.43,1047 5492,1249.57 5492,1458 5534,1500 R120.2@5682.6,1500
  other v1: 5965.55,1537.45 5876.55,1538.45 5966.55,1626.45 5877.55,1627.45 5967.55,1715.45 5878.55,1716.45
U_PHASE_REF: R79.1 R120.1 TP32.1 U24.21 U24.22 U24.23 | length 3865
  Top Layer w15: R79.1@2156,976 2187,976 2203,960 2342.57,960 2461.57,1079 5279,1079 5462,1262 5462,1459 5421,1500 R120.1@5257.4,1500
  Top Layer w50: R120.1@5257.4,1495 R120.1@5257.4,1500 ; TP32.1@5257.4,1757.4 TP32.1@5260,1760
U_TOP: C74.1 R15.2 R18.2 R21.2 R112.2 TP17.1 U24.9 | length 685.5
  Top Layer w30: R21.2@2322.09,1231.97 R18.2@2322.09,1336.97 ; R15.2@2322.09,1441.97 R15.2@2322.09,1440.97 R18.2@2322.09,1336.97 ; U24.9@2761.14,1424.96 2712.68,1376.5 C74.1@2670,1376.5 R112.2@2605,1376.5 2413.5,1376.5 2373.97,1336.97 R18.2@2322.09,1336.97
V_BOT: C76.1 R35.2 R37.2 R38.2 R39.2 TP21.1 U24.7 | length 679
  Top Layer w30: R39.2@2321.09,1850 R37.2@2321.09,1955 ; R35.2@2321.09,2060 R37.2@2321.09,1955 ; U24.7@2761.14,2024.96 2712.68,1976.5 C76.1@2670,1976.5 R38.2@2605,1976.5 2393,1976.5 2371.5,1955 R37.2@2321.09,1955
V_TOP: C73.1 R29.2 R31.2 R32.2 R33.2 TP14.1 U24.5 | length 671
  Top Layer w30: R33.2@2322.09,2466.97 R31.2@2322.09,2571.97 ; R29.2@2322.09,2676.97 R29.2@2322.09,2675.97 R31.2@2322.09,2571.97 ; U24.5@2761.14,2624.96 2712.68,2576.5 C73.1@2670,2576.5 R32.2@2605,2576.5 2326.61,2576.5 R31.2@2322.09,2571.97
VCC: C32.1 C33.1 C34.1 C35.1 C46.1 C47.1 C48.1 C49.1 C52.1 C53.1 C56.1 D12.2 D13.2 D14.2 J7.1 R110.1 U2.5 U6.5 U8.5 U10.5 | length 7501.9
  Top Layer w25: U10.5@1944.57,5075 1944.57,4996.06 C48.1@1943.5,4995 1943.5,4916.5 C49.1@1945,4915 1945,4855 1960,4840 v1(2520,4840)
  Top Layer w30: R110.1@2764.83,-350.68 v1(2764.83,-270)
  PWR w60: v1(2520,4840) 2520,3895 2268,3643 v1(2268,3418) 2586,3100 2586,2740 2277,2431 v1(2277,2156) 2570,1863 2570,1490 2466,1386 2466,621 2316,471 2316,407 2104.5,195.5 1994.5,195.5 1939,140 v1(1939,42) 2012,-31 2619,-31 2764.83,-176.83 v1(2764.83,-270)
  other v1: 1922,1794 1967,1794 1923,3029 1968,3029
VCC_UT: C21.2 C23.1 C26.1 C50.1 J6.1 R41.1 U5.5 U22.2 | length 676.2
  GND w30: v1(1968,1169.97) v1(1923,1169.97) 1923,832.32 2124,631.32 v1(2124,622)
VCC_VT: C40.1 C41.1 C54.1 J13.1 R42.1 U7.5
  other v1: 1923,2404.97 1968,2404.97
VCC_WT: C3.1 C4.1 C51.1 C71.2 J5.1 R43.1 U1.5 U20.2
  other v1: 1923,3643 1968,3643
VDC+: C111.1 C112.1 D9.1 D10.1 J3.2 J8.1 R45.1 R98.2 TP25.1 TP26.1 TP27.1 U24.16 U24.17 U24.18 U24.30 U24.31 U24.32 | length 619.5
  GND w50: TP25.1@4040,160 4150,160 ; TP26.1@4040,4384 4124,4384 4125,4385
  Bottom Layer w30: U24.16@4126.69,-75.24 4172.75,-121.29 D10.1@4172.75,-300.55 4172.75,-479.34 R98.2@4172.09,-480
VDC-: C12.1 C13.1 C28.1 C31.1 C32.2 C33.2 C34.2 C35.2 C43.1 C45.1 C46.2 C47.2 C48.2 C49.2 C64.1 C67.1 C75.2 C76.2 C77.2 C79.2 C82.1 C91.1 C94.1 C95.2 C96.2 C97.2 C111.2 C112.2 J7.2 R5.2 R10.2 R12.1 R22.2 R24.2 R26.1 R34.2 R36.2 R38.1 R51.1 R91.1 R107.1 R109.1 TP20.1 TP22.1 TP24.1 TP33.1 TP34.1 TP35.1 TP36.1 U9.2 U10.8 U12.4 U15.4 U23.1 U24.4 U24.8 U24.12 U24.13 U24.14 U24.15 U24.20 U24.33 U24.34 U24.35 XF1.1 XF1.2 | length 8400
  Top Layer w15: U15.4@1944.3,-260.55 2019.73,-260.55 v1(2039.73,-240.55) R91.1@2113.24,-240.55 ; U10.8@1944.91,5224.75 2015.06,5224.75 2014.81,5225 v1(2013,5225) ; U9.2@2324.29,-405 v1(2380,-405)
  Top Layer w20: v1(1943.73,-646.55) 1944.3,-647.12 U12.4@1944.3,-688.55 ; C48.2@2006.5,4995 v1(2055,4995) v1@2057.01,4995 ; C49.2@2025,4915 v1(2085,4915) ; C91.1@2106.23,-430.55 2106.23,-495.23 C67.1@2119,-508 v1(2119,-572) ; R107.1@2238,-682.99 C94.1@2303,-682.99 v1(2303,-749) ; v1(2301.5,-553) C79.2@2301.5,-490 ; TP36.1@2428,-219 2460,-187 3083,-187 3964,694 4986.87,694 U24.20@5042.64,749.76 ; v1(2508.33,-657.68) C95.2@2577.33,-657.68 ; v1(2577.33,-726.68) C95.2@2577.33,-657.68 ; C95.2@2591.47,-643.55 C95.2@2577.33,-657.68 ; U23.1@2739.73,-578.55 2739.73,-527.78 C97.2@2764.83,-502.68 ; C96.2@2787.33,-426.68 2787.33,-480.18 C97.2@2764.83,-502.68 ; v1(2795,-617) 2795,-532.86 C97.2@2764.83,-502.68
  Top Layer w30: C46.2@2013.5,1850 2049,1814.5 v1(2049,1794) ; C34.2@2014.5,97 2066.5,45 v1(2136,45) ; C32.2@2014.5,3085 2036,3063.5 v1(2036,3029) ; C82.1@2093.76,-835.95 2101,-843.18 C64.1@2101,-912 v1(2171,-912) ; v1(2305,5265) 2385,5265 2515,5395 3371,5395 XF1.2@3698,5722 ; R12.1@2601,700.5 C75.2@2670,700.5 2735.21,700.5 U24.12@2761.14,674.57 2800.71,635 TP20.1@2890,635 ; R38.1@2605,1913.5 C76.2@2670,1913.5 2722.2,1913.5 U24.8@2761.14,1874.57 2810.71,1825 TP22.1@2890,1825 ; R26.1@2605,3113.5 C77.2@2670,3113.5 2722.2,3113.5 U24.4@2761.14,3074.57 2800.71,3035 TP24.1@2890,3035
  GND w50: U24.4@2761.14,3050.86 U24.4@2761.14,3074.57 ; 3675,160 TP33.1@3770,160 ; 3698,4384 TP34.1@3770,4384
  GND w100: 2794,-515 C111.2@3358.66,-515
  Bottom Layer w30: C47.2@2023,1850 2050.12,1822.88 2050.12,1795.12 v1(2049,1794) ; C35.2@2024,97 2076,45 v1(2136,45) ; C33.2@2024,3085 2036,3073 v1(2036,3029) ; R109.1@3213,-516.01 3214.01,-515 C111.2@3358.66,-515
  other v1: 2127,2245 2082,2246 2128,3480 2083,3481
VDC-_F: C78.2 J8.2 Q1.3 R96.1 XF2.1 XF2.2 | length 385.8
  Top Layer w30: R96.1@5589,5718 C78.2@5654,5718 5654,5817 5738,5901 Q1.3@5841,5901
VEE: C52.2 C53.2 C56.2 J7.3 R101.1 R102.1 R105.1 | length 3792.6
  PWR w60: v1@2109,3412 v1(2153,3412) 2511,3054 2511,2779 2192,2460 2192,2182 v1(2185,2175) 2185,2118 2491,1812 2491,1529 2380.5,1418.5 2380.5,1081.5 2103,804 2034,804 1949,719 1949,535 2023,461 J7.3@2115,461
  other v1: 2108,3413
VEE_UT: C50.2 J6.3 R99.1
VEE_VT: C54.2 J13.3 R103.1
VEE_WT: C51.2 J5.3 R100.1
W_BOT: C77.1 R9.2 R11.2 R13.2 R26.2 TP23.1 U24.3 | length 674.7
  Top Layer w30: R13.2@2322.09,3085 R11.2@2322.09,3190 ; R9.2@2322.09,3295 R11.2@2322.09,3190 ; U24.3@2761.14,3224.96 2712.68,3176.5 C77.1@2670,3176.5 R26.2@2605,3176.5 2335.59,3176.5 R11.2@2322.09,3190
W_PHASE: J4.3 R86.1 R118.2 | length 4508.1
  Top Layer w15: R86.1@2161.23,4471.58 2174.23,4484.58 2538.43,4484.58 2735.85,4682 2980,4682 4642,3020 5416.43,3020 5492,3095.57 5492,3258 5534,3300 R118.2@5682.6,3300
  other v1: 5878.55,3078.55 5967.55,3079.55 5877.55,3167.55 5966.55,3168.55 5876.55,3256.55 5965.55,3257.55
W_PHASE_REF: R85.1 R118.1 TP28.1 TP29.1 U24.27 U24.28 U24.29 | length 4768.1
  Top Layer w15: R85.1@2161.23,4536.58 2183.23,4514.58 2526,4514.58 2723.42,4712 2992,4712 4654,3050 5404,3050 5462,3108 5462,3259 5421,3300 R118.1@5257.4,3300
  Top Layer w50: TP29.1@5257.4,3557.4 TP29.1@5260,3560
  GND w50: TP28.1@4755,3450 4755.24,3449.76 U24.29@5042.64,3449.76
W_TOP: C72.1 R3.2 R17.2 R19.2 R20.2 TP12.1 U24.1 | length 683
  Top Layer w30: R19.2@2322.09,3705 R17.2@2322.09,3810 ; R3.2@2322.09,3915 R17.2@2322.09,3810 ; U24.1@2761.14,3824.96 2712.68,3776.5 C72.1@2670,3776.5 R20.2@2605,3776.5 2408.5,3776.5 2375,3810 R17.2@2322.09,3810
pads on no net: FID1.1 FID2.1 FID3.1 FID4.1 FID5.1 FID6.1 H1.1 H2.1 H3.1 H4.1 H5.0 H6.0 H7.0 H8.0 J1.9 J1.11 J1.21 J1.27 LBL1.0 U3.8 U4.1 U23.4 U23.5 U24.MH1 U24.MH2 U24.MH3 U24.MH4

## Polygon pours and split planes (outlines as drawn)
W_TOP on Top Layer "W_TOP_L01_P819" (solid, remove dead copper, pour order 819): 2287,3954 2287,3670 2298,3659 2439,3659 2526,3746 2532,3752 2590,3752 2896,3752 2939,3795 2939,3921 2893,3967 2300,3967
GND_UT on Top Layer "Top Layer-MU" (solid, remove dead copper, pour order 852): 21 vertices, not listed, extent 1990,1481.97 2248,1651.97
GND_VT on Top Layer "Top Layer-MU" (solid, remove dead copper, pour order 571): 21 vertices, not listed, extent 1990,2720.97 2248,2890.97
GND_WT on Top Layer "GND_WT_L01_P850" (solid, remove dead copper, pour order 850): 37 vertices, not listed, extent 1906,3959 2248,4332
V_TOP on Top Layer "V_TOP_L01_P821" (solid, remove dead copper, pour order 821): 2287,2714 2287,2429 2302,2414 2420,2414 2543,2537 2557,2551 2616,2551 2880,2551 2932,2603 2932,2675 2933,2676 2933,2697 2892,2738 2311,2738
U_PHASE_REF on Top Layer "Top Layer-MU" (solid, remove dead copper, pour order 777): 5342,1794 5024,1794 4990,1760 4990,1320 5010,1300 5350,1300 5365,1315 5365,1771
U_PHASE on Top Layer "Top Layer-MU" (solid, remove dead copper, pour order 755): 5576,1322 5576,1681 5957,2062 6165,2062 6195,2032 6195,1710 5789,1304 5594,1304
W_PHASE on Top Layer "Top Layer-MU" (solid, remove dead copper, pour order 731): 5576,3475 5576,3109 5957,2728 6165,2728 6195,2758 6195,3080 5789,3486 5587,3486
GND_UT on Top Layer "Top Layer-MU" (solid, remove dead copper, pour order 641): 2184.77,780.55 2184.77,645.55 2189.77,640.55 2284.77,640.55 2289.77,645.55 2289.77,780.55 2284.77,785.55 2189.77,785.55 2184.77,780.55
VCC_UT on Top Layer "Top Layer-MU" (solid, remove dead copper, pour order 639): 2104.77,740.55 2104.77,605.55 2109.77,600.55 2159.77,600.55 2164.77,605.55 2164.77,735.55 2159.77,740.55
GND_UT on Top Layer "Top Layer-MU" (solid, remove dead copper, pour order 637): 1926.77,762.55 1920.77,756.55 1920.77,664.55 1925.77,659.55 2065.77,659.55 2071.77,665.55 2071.77,751.55 2060.77,762.55 1995.77,762.55
NetC85_2 on Top Layer "Top Layer-MU" (solid, remove dead copper, pour order 635): 2159.77,785.55 1919.77,785.55 1909.77,795.55 1904.77,800.55 1904.77,885.55 1909.77,890.55 1979.77,890.55 2014.77,855.55 2154.77,855.55 2164.77,845.55 2164.77,790.55 2159.77,785.55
